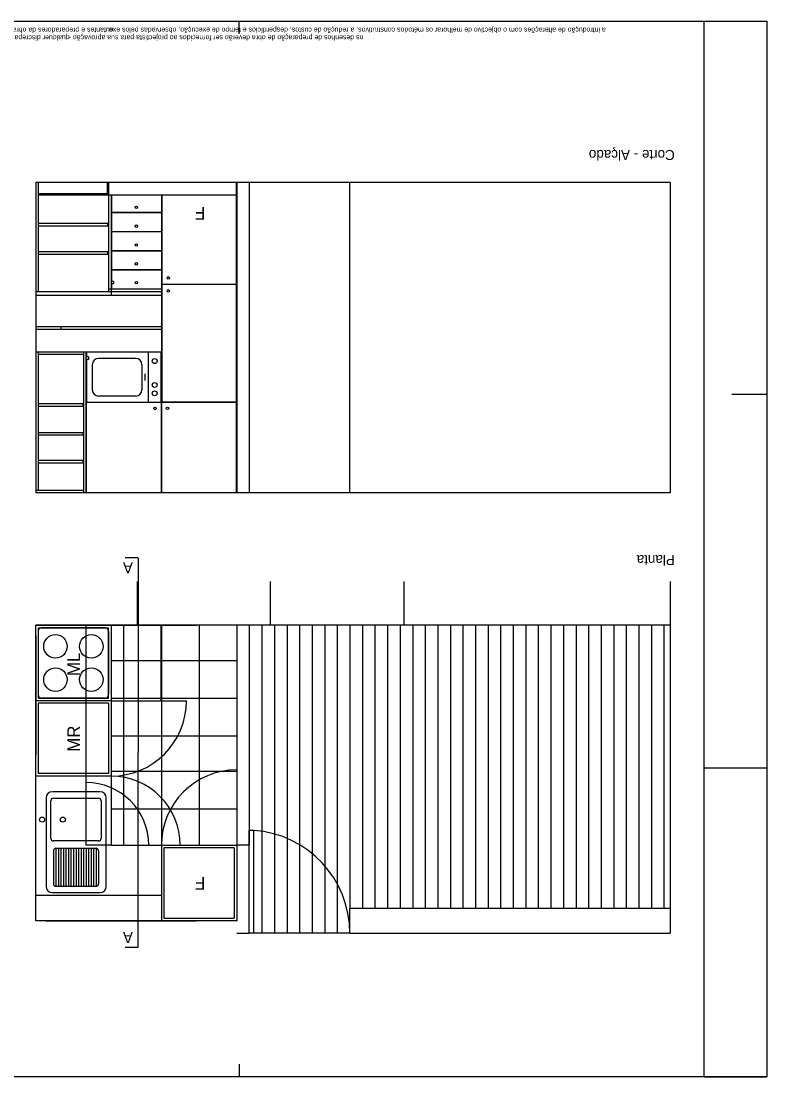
# Model space of a CAD drawing. Extents: x 1327 to 1338.6, y -310.7 to -302.3.
# Drawn here: x 1332.65 to 1338.59, y -310.66 to -302.26 of the extents above; entities that cross this region are included whole.
import ezdxf

# ---------------------------------------------------------------- set-up
doc = ezdxf.new("R2010")
doc.units = 0
for name, color, linetype in [('Level 1', 7, 'Continuous'), ('Level 10', 7, 'Continuous'), ('Level 11', 7, 'Continuous'), ('Level 13', 7, 'Continuous'), ('Level 2', 7, 'Continuous'), ('Level 3', 7, 'Continuous'), ('Level 4', 7, 'Continuous'), ('Level 59', 7, 'Continuous'), ('Level 60', 7, 'Continuous'), ('Level 62', 7, 'Continuous')]:
    doc.layers.add(name, color=color, linetype=linetype)

msp = doc.modelspace()

# ---------------------------------------------------------------- linework, layer by layer
at = {"layer": 'Level 1'}
for p, q in [((1334.4675, -303.547), (1332.7675, -303.547)), ((1332.7675, -303.547), (1332.7675, -306.017)), ((1332.7875, -303.547), (1332.7875, -304.417)), ((1333.3375, -303.547), (1333.3375, -303.647)), ((1333.3475, -303.547), (1333.3475, -304.417)), ((1337.8178, -303.547), (1334.4675, -303.547)), ((1337.8178, -303.547), (1337.8178, -306.017)), ((1333.3375, -303.637), (1332.7875, -303.637)), ((1333.3675, -303.647), (1332.7875, -303.647)), ((1333.3675, -303.647), (1333.3675, -304.447)), ((1332.7875, -303.872), (1333.3415, -303.872)), ((1332.7875, -303.892), (1333.3415, -303.892)), ((1333.3415, -303.892), (1333.3415, -303.872)), ((1332.7875, -304.097), (1333.3415, -304.097)), ((1332.7875, -304.117), (1333.3415, -304.117)), ((1333.3415, -304.117), (1333.3415, -304.097)), ((1333.3675, -304.397), (1333.3475, -304.397)), ((1333.3865, -304.335), (1333.3675, -304.335)), ((1333.3865, -304.355), (1333.3675, -304.355)), ((1333.3865, -304.335), (1333.3865, -304.355)), ((1333.3675, -304.417), (1332.7675, -304.417)), ((1333.3675, -304.447), (1332.7675, -304.447)), ((1333.1675, -304.897), (1332.7675, -304.897)), ((1332.7875, -304.897), (1332.7875, -305.997)), ((1333.1475, -304.917), (1332.7875, -304.917)), ((1333.1475, -304.897), (1333.1475, -306.017)), ((1333.1675, -304.897), (1333.1675, -306.017)), ((1333.1875, -304.935), (1333.1675, -304.935)), ((1333.1875, -304.955), (1333.1675, -304.955)), ((1333.1875, -304.935), (1333.1875, -304.955)), ((1332.7875, -305.307), (1333.1425, -305.307)), ((1332.7875, -305.327), (1333.1425, -305.327)), ((1333.1425, -305.307), (1333.1425, -305.327)), ((1333.1425, -305.5387), (1332.7875, -305.5387)), ((1333.1425, -305.5587), (1332.7875, -305.5587)), ((1333.1425, -305.5387), (1333.1425, -305.5587)), ((1333.1425, -305.7603), (1332.7875, -305.7603)), ((1333.1425, -305.7803), (1332.7875, -305.7803)), ((1333.1425, -305.7603), (1333.1425, -305.7803)), ((1333.1475, -305.997), (1332.7675, -305.997)), ((1334.4675, -306.017), (1332.7675, -306.017)), ((1337.8178, -306.017), (1334.4675, -306.017)), ((1333.5773, -307.0708), (1333.5773, -306.7208)), ((1334.6373, -307.0708), (1334.6373, -306.7208)), ((1335.6975, -306.7208), (1335.6975, -307.0708)), ((1337.8178, -306.7208), (1337.8178, -307.0708)), ((1337.8178, -306.7208), (1337.8178, -307.0708)), ((1332.7675, -309.4208), (1332.7675, -307.0708)), ((1333.5773, -307.0708), (1332.7675, -307.0708)), ((1335.6975, -307.0708), (1334.6373, -307.0708)), ((1337.8178, -307.0708), (1337.8178, -309.5208)), ((1334.4675, -309.5208), (1334.4675, -308.8208)), ((1334.3675, -309.5208), (1334.4675, -309.5208))]:
    msp.add_line(p, q, dxfattribs=at)
msp.add_lwpolyline([(1334.4675, -308.8208), (1334.3675, -308.8208), (1334.3675, -309.4208), (1332.7675, -309.4208)], dxfattribs=at)
at = {"layer": 'Level 10'}
for p, q in [((1333.4675, -307.0708), (1333.4675, -308.8208)), ((1333.7675, -307.0708), (1333.7675, -308.8208)), ((1334.0675, -307.0708), (1334.0675, -308.8208)), ((1334.3675, -307.0708), (1334.3675, -308.8208)), ((1334.4675, -307.0708), (1334.4675, -308.8208)), ((1334.5675, -307.0708), (1334.5675, -309.5208)), ((1334.6675, -307.0708), (1334.6675, -309.5208)), ((1334.7675, -307.0708), (1334.7675, -309.5208)), ((1334.8675, -307.0708), (1334.8675, -309.5208)), ((1334.9675, -307.0708), (1334.9675, -309.5208)), ((1335.0675, -307.0708), (1335.0675, -309.5208)), ((1335.1675, -307.0708), (1335.1675, -309.5208)), ((1335.2675, -307.0708), (1335.2675, -309.3208)), ((1335.3675, -307.0708), (1335.3675, -309.3208)), ((1335.4675, -307.0708), (1335.4675, -309.3208)), ((1335.5675, -307.0708), (1335.5675, -309.3208)), ((1335.6675, -307.0708), (1335.6675, -309.3208)), ((1335.7675, -307.0708), (1335.7675, -309.3208)), ((1335.8675, -307.0708), (1335.8675, -309.3208)), ((1335.9675, -307.0708), (1335.9675, -309.3208)), ((1336.0675, -307.0708), (1336.0675, -309.3208)), ((1336.1675, -307.0708), (1336.1675, -309.3208)), ((1336.2675, -307.0708), (1336.2675, -309.3208)), ((1336.3675, -307.0708), (1336.3675, -309.3208)), ((1336.4675, -307.0708), (1336.4675, -309.3208)), ((1336.5675, -307.0708), (1336.5675, -309.3208)), ((1336.6675, -307.0708), (1336.6675, -309.3208)), ((1336.7675, -307.0708), (1336.7675, -309.3208)), ((1336.8675, -307.0708), (1336.8675, -309.3208)), ((1336.9675, -307.0708), (1336.9675, -309.3208)), ((1337.0675, -307.0708), (1337.0675, -309.3208)), ((1337.1675, -307.0708), (1337.1675, -309.3208)), ((1337.2675, -307.0708), (1337.2675, -309.3208)), ((1337.3675, -307.0708), (1337.3675, -309.3208)), ((1337.4675, -307.0708), (1337.4675, -309.3208)), ((1337.5675, -307.0708), (1337.5675, -309.3208)), ((1337.6675, -307.0708), (1337.6675, -309.3208)), ((1337.7675, -307.0708), (1337.7675, -309.3208)), ((1333.3675, -307.3508), (1334.3675, -307.3508)), ((1333.3675, -307.6508), (1334.3675, -307.6508)), ((1333.3675, -307.9508), (1334.3675, -307.9508)), ((1333.3675, -308.2308), (1334.3675, -308.2308)), ((1333.3675, -308.5308), (1334.3675, -308.5308))]:
    msp.add_line(p, q, dxfattribs=at)
at = {"layer": 'Level 11'}
for p, q in [((1333.3175, -307.0907), (1332.8175, -307.0907)), ((1332.7875, -307.1207), (1332.7875, -307.6207)), ((1333.3475, -307.1207), (1333.3475, -307.6207)), ((1333.3175, -307.6507), (1332.8175, -307.6507)), ((1332.9085, -308.4466), (1333.2685, -308.4466)), ((1332.8885, -308.7666), (1332.8885, -308.4666)), ((1333.2885, -308.4666), (1333.2885, -308.7666)), ((1333.2685, -308.7866), (1332.9085, -308.7866)), ((1332.9085, -308.865), (1332.9085, -309.1266)), ((1332.9285, -308.845), (1333.2485, -308.845)), ((1332.9285, -308.845), (1332.9285, -309.1466)), ((1332.9485, -308.845), (1332.9485, -309.1466)), ((1332.9685, -308.845), (1332.9685, -309.1466)), ((1332.9885, -308.845), (1332.9885, -309.1466)), ((1333.0085, -308.845), (1333.0085, -309.1466)), ((1333.0285, -308.845), (1333.0285, -309.1466)), ((1333.0485, -308.845), (1333.0485, -309.1466)), ((1333.0685, -308.845), (1333.0685, -309.1466)), ((1333.0885, -308.845), (1333.0885, -309.1466)), ((1333.1085, -308.845), (1333.1085, -309.1466)), ((1333.1285, -308.845), (1333.1285, -309.1466)), ((1333.1485, -308.845), (1333.1485, -309.1466)), ((1333.1685, -308.845), (1333.1685, -309.1466)), ((1333.1885, -308.845), (1333.1885, -309.1466)), ((1333.2085, -308.845), (1333.2085, -309.1466)), ((1333.2285, -308.845), (1333.2285, -309.1466)), ((1333.2485, -308.845), (1333.2485, -309.1466)), ((1333.2685, -308.865), (1333.2685, -309.1266)), ((1334.3475, -308.8408), (1333.7875, -308.8408)), ((1333.7875, -308.8408), (1333.7875, -309.4008)), ((1334.3475, -308.8408), (1334.3475, -309.4008)), ((1332.9285, -309.1466), (1333.2485, -309.1466)), ((1333.7875, -309.4008), (1334.3475, -309.4008))]:
    msp.add_line(p, q, dxfattribs=at)
for points in [[(1332.8507, -308.4454), (1332.8507, -309.1468)], [(1333.2791, -308.3954), (1332.9007, -308.3954)], [(1333.3291, -309.1468), (1333.3291, -308.4454)], [(1332.9007, -309.1968), (1333.2791, -309.1968)]]:
    msp.add_lwpolyline(points, dxfattribs=at)
for centre, radius in [((1332.9249, -307.2386), 0.0936), ((1333.2101, -307.2386), 0.0936), ((1332.9249, -307.5028), 0.0936), ((1333.2101, -307.5028), 0.0936), ((1332.8185, -308.6166), 0.0199), ((1332.9845, -308.6166), 0.0199)]:
    msp.add_circle(centre, radius, dxfattribs=at)
for centre, radius, start, end in [((1332.8175, -307.1207), 0.03, 89.99985, 180.0002), ((1333.3175, -307.1207), 0.03, 0.00009, 90.0001), ((1332.8175, -307.6207), 0.03, 180.00021, 269.99999), ((1333.3175, -307.6207), 0.03, 270.00005, 0.00002), ((1332.9007, -308.4454), 0.05, 90, 180), ((1332.9085, -308.4666), 0.02, 90, 180), ((1333.2685, -308.4666), 0.02, 0, 90), ((1333.2791, -308.4454), 0.05, 0, 90), ((1332.9085, -308.7666), 0.02, 180, 270), ((1333.2685, -308.7666), 0.02, 270, 0), ((1332.9285, -308.865), 0.02, 90, 180), ((1333.2485, -308.865), 0.02, 0, 90), ((1332.9007, -309.1468), 0.05, 180, 270), ((1332.9285, -309.1266), 0.02, 180, 270), ((1333.2485, -309.1266), 0.02, 270, 0), ((1333.2791, -309.1468), 0.05, 270, 0)]:
    msp.add_arc(centre, radius, start, end, dxfattribs=at)
at = {"layer": 'Level 13'}
for p, q in [((1334.3625, -303.547), (1334.3625, -305.2965)), ((1335.2678, -306.016), (1335.2678, -303.547)), ((1333.7675, -303.647), (1333.3675, -303.647)), ((1333.3695, -303.647), (1333.3695, -304.335)), ((1334.3625, -303.647), (1333.7675, -303.647)), ((1333.7675, -303.647), (1333.7675, -305.157)), ((1333.7725, -303.647), (1333.7725, -305.2965)), ((1333.7675, -303.787), (1333.3695, -303.787)), ((1333.7675, -303.789), (1333.3695, -303.789)), ((1333.7675, -303.939), (1333.3695, -303.939)), ((1333.7675, -303.941), (1333.3695, -303.941)), ((1333.7675, -304.091), (1333.3695, -304.091)), ((1333.7675, -304.093), (1333.3695, -304.093)), ((1333.7675, -304.243), (1333.3695, -304.243)), ((1333.7675, -304.245), (1333.3695, -304.245)), ((1333.7675, -304.397), (1333.3675, -304.397)), ((1333.3695, -304.355), (1333.3695, -304.395)), ((1333.7675, -304.395), (1333.3695, -304.395)), ((1334.3625, -304.358), (1333.7725, -304.358)), ((1334.3625, -304.36), (1333.7725, -304.36)), ((1333.7675, -304.417), (1333.3675, -304.417)), ((1333.7675, -304.447), (1333.3675, -304.447)), ((1333.7675, -304.697), (1332.7675, -304.697)), ((1333.7675, -304.717), (1332.7675, -304.717)), ((1332.9675, -304.697), (1332.9675, -304.717)), ((1333.7675, -304.897), (1333.1675, -304.897)), ((1333.1725, -304.897), (1333.1725, -304.935)), ((1333.6625, -304.897), (1333.6625, -305.297)), ((1333.7625, -304.897), (1333.7625, -305.297)), ((1333.1725, -304.955), (1333.1725, -305.297)), ((1333.2175, -304.997), (1333.2175, -305.197)), ((1333.5625, -304.947), (1333.2675, -304.947)), ((1333.6125, -304.997), (1333.6125, -305.197)), ((1333.637, -305.0702), (1333.637, -305.1237)), ((1333.7675, -305.157), (1333.7675, -306.017)), ((1333.5625, -305.247), (1333.2675, -305.247)), ((1333.7675, -305.299), (1333.1675, -305.299)), ((1333.1695, -305.299), (1333.1695, -306.017)), ((1333.7625, -305.297), (1333.1725, -305.297)), ((1333.7655, -305.299), (1333.7655, -306.017)), ((1334.3625, -305.299), (1333.7675, -305.299)), ((1334.3625, -305.2965), (1333.7725, -305.2965)), ((1334.3625, -305.299), (1334.3625, -306.017)), ((1337.8178, -306.016), (1334.4675, -306.016)), ((1334.4675, -309.5208), (1334.4675, -308.7027)), ((1334.5025, -308.7027), (1334.4675, -308.7027)), ((1334.5025, -309.5208), (1334.5025, -308.7027)), ((1335.2678, -309.3208), (1337.8178, -309.3208)), ((1335.2678, -309.5208), (1335.2678, -309.3208)), ((1334.5025, -309.5208), (1334.4675, -309.5208)), ((1335.2675, -309.5208), (1337.8178, -309.5208)), ((1335.2678, -309.5208), (1337.8178, -309.5208))]:
    msp.add_line(p, q, dxfattribs=at)
for centre, radius in [((1333.5685, -303.745), 0.01), ((1333.5685, -303.895), 0.01), ((1333.5685, -304.045), 0.01), ((1333.5685, -304.195), 0.01), ((1333.8225, -304.3066), 0.01), ((1333.5685, -304.345), 0.01), ((1333.8225, -304.41), 0.01), ((1333.7143, -304.968), 0.02), ((1333.7143, -305.1587), 0.02), ((1333.7143, -305.2251), 0.02), ((1333.7175, -305.345), 0.01), ((1333.8164, -305.3449), 0.01)]:
    msp.add_circle(centre, radius, dxfattribs=at)
for centre, start, end in [((1333.2675, -304.997), 90, 180), ((1333.5625, -304.997), 0, 90), ((1333.2675, -305.197), 180, 270), ((1333.5625, -305.197), 270, 0)]:
    msp.add_arc(centre, 0.05, start, end, dxfattribs=at)
at = {"layer": 'Level 2'}
for p, q in [((1334.3675, -303.547), (1334.3675, -306.017)), ((1334.4675, -303.547), (1334.4675, -306.017)), ((1333.3675, -307.0708), (1333.3675, -308.8208)), ((1333.3675, -307.0708), (1333.3675, -308.8208)), ((1333.3675, -307.0708), (1333.3675, -308.8208)), ((1334.6373, -307.0708), (1333.5773, -307.0708)), ((1337.8178, -307.0708), (1335.6975, -307.0708)), ((1333.3675, -308.8208), (1334.3675, -308.8208)), ((1333.3675, -308.8208), (1334.3675, -308.8208)), ((1333.3675, -308.8208), (1334.3675, -308.8208)), ((1333.7675, -308.8208), (1333.7675, -309.4208))]:
    msp.add_line(p, q, dxfattribs=at)
at = {"layer": 'Level 3'}
for p in [(1333.1675, -307.0708), (1333.3675, -308.8208)]:
    msp.add_line(p, (1333.1675, -308.8208), dxfattribs=at)
msp.add_arc((1333.3682, -307.831), 0.4426, 270, 270.00000277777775, dxfattribs=at)
at = {"layer": 'Level 4'}
for p, q in [((1332.7675, -307.0708), (1333.3675, -307.0708)), ((1332.7875, -307.0908), (1333.3475, -307.0908)), ((1332.7875, -307.0908), (1332.7875, -307.6508)), ((1333.3475, -307.6508), (1333.3475, -307.0908)), ((1333.766, -307.6708), (1333.766, -307.0708)), ((1333.3675, -307.6708), (1332.7675, -307.6708)), ((1333.3675, -307.6708), (1332.7675, -307.6708)), ((1332.7875, -307.6508), (1333.3475, -307.6508)), ((1333.3475, -307.6908), (1332.7875, -307.6908)), ((1332.7875, -307.6908), (1332.7875, -308.2508)), ((1333.3475, -307.6908), (1333.3475, -308.2508)), ((1333.3675, -307.6708), (1333.9675, -307.6708)), ((1333.3675, -308.2708), (1332.7675, -308.2708)), ((1333.3675, -308.2708), (1332.7675, -308.2708)), ((1333.3475, -308.2508), (1332.7875, -308.2508)), ((1333.7675, -309.2208), (1332.7675, -309.2208)), ((1335.2675, -309.5208), (1334.5025, -309.5208))]:
    msp.add_line(p, q, dxfattribs=at)
for centre, radius, start, end in [((1333.3675, -307.6708), 0.6, 270, 0), ((1333.3675, -308.8208), 0.55, 0, 90), ((1334.3675, -308.8208), 0.6, 90, 180), ((1333.1675, -308.8208), 0.5, 0, 90)]:
    msp.add_arc(centre, radius, start, end, dxfattribs=at)
msp.add_ellipse((1334.447, -309.5208), major_axis=(-0.8205, 0), ratio=0.99938, start_param=3.141593, end_param=4.644683, dxfattribs=at)
at = {"layer": 'Level 59'}
for p, q in [((1333.5802, -306.5346), (1333.4804, -306.5346)), ((1333.5818, -306.5346), (1333.5802, -309.6334)), ((1333.5802, -309.6334), (1333.4804, -309.6334))]:
    msp.add_line(p, q, dxfattribs=at)
at = {"layer": 'Level 62'}
for p, q in [((1334.3868, -302.3635), (1334.3868, -302.2635)), ((1338.0864, -310.6635), (1338.0864, -302.2635)), ((1338.5864, -305.2335), (1338.3064, -305.2335)), ((1332.8478, -307.0708), (1334.0475, -307.0708)), ((1332.7678, -307.1508), (1332.7678, -308.1008)), ((1332.7678, -307.1508), (1332.7678, -308.1008)), ((1337.8178, -307.1508), (1337.8178, -308.1008)), ((1337.8178, -307.1508), (1337.8178, -307.5695)), ((1338.0864, -308.2035), (1338.5864, -308.2035)), ((1332.7675, -309.3408), (1332.7675, -308.3408)), ((1332.7675, -309.3408), (1332.7675, -308.3408)), ((1332.8475, -309.4208), (1334.0475, -309.4208)), ((1334.386, -310.5635), (1334.386, -310.6635)), ((1338.0864, -310.6635), (1338.5864, -310.6635))]:
    msp.add_line(p, q, dxfattribs=at)
msp.add_lwpolyline([(1338.5864, -302.2635), (1338.5864, -310.6635), (1326.9868, -310.6635), (1326.9868, -302.2635)], close=True, dxfattribs=at)

# ---------------------------------------------------------------- texts
at = {"layer": 'Level 11'}
for s, rotation, p in [('F', 180, (1334.1167, -303.7425)), ('ML', 90, (1333.1198, -307.474)), ('MR', 90, (1333.1198, -308.0764)), ('F', 180, (1334.1167, -309.0742))]:
    msp.add_text(s, height=0.1, rotation=rotation, dxfattribs=at).set_placement(p)
at = {"layer": 'Level 59'}
for rotation, p in [(180.00018, (1333.5411, -306.5692)), (179.99982, (1333.5411, -309.5108))]:
    msp.add_text('A', height=0.088, rotation=rotation, dxfattribs=at).set_placement(p)
at = {"layer": 'Level 60'}
for s, height, rotation, p in [('cutantes e preparadores da obra deverão ser sugeridas. não poderão no entanto ser implementadas sem o consentimento expresso dos responsáveis pela arquitectura', 0.0399996, 180, (1333.3847, -302.3155)), ('a introdução de alterações com o objectivo de melhorar os métodos construtivos, a redução de custos, desperdícios e tempo de execução, observadas pelos exe', 0.0399996, 180, (1337.3045, -302.3155)), ('qualquer discrepancia ou incoerencia detectada deverá ser comunicada aos responsáveis pela arquitectura com o objectivo de ser analizada e corrigida -', 0.0399996, 180, (1333.0381, -302.3765)), ('os desenhos de preparação de obra deverão ser fornecidos ao projectista para sua aprovação -', 0.04, 180, (1335.3755, -302.3765)), ('Corte - Alçado', 0.08, 180.00001, (1337.8534, -303.2886)), ('Planta', 0.08, 180.00001, (1337.8539, -306.512))]:
    msp.add_text(s, height=height, rotation=rotation, dxfattribs=at).set_placement(p)

doc.saveas('drawing.dxf')
